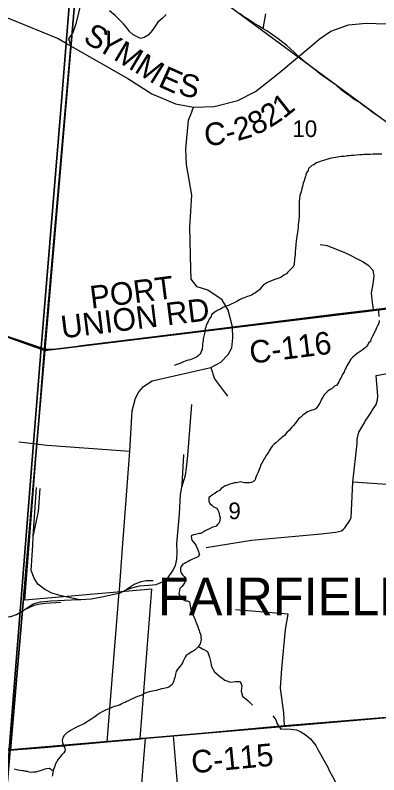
# Model space of a CAD drawing. Extents: x 0 to 34, y 0 to 22.
# Drawn here: x 3.482 to 4.396, y 16.296 to 18.207 of the extents above; entities that cross this region are included whole.
import ezdxf

# ---------------------------------------------------------------- set-up
doc = ezdxf.new("R2010")
doc.units = 0
for name, color, linetype in [('Default', 7, 'Continuous'), ('GM_X_Corporation_Text', 7, 'Continuous'), ('GM_X_County_Road', 7, 'Continuous'), ('GM_X_County_Road_Text', 7, 'Continuous'), ('GM_X_Minor_River', 7, 'Continuous'), ('GM_X_Rail_Line', 7, 'Continuous'), ('GM_X_Section', 7, 'Continuous'), ('GM_X_Section_Text', 7, 'Continuous'), ('GM_X_Township_Road', 7, 'Continuous')]:
    doc.layers.add(name, color=color, linetype=linetype)

msp = doc.modelspace()

# ---------------------------------------------------------------- linework, layer by layer
at = {"layer": 'Default'}
msp.add_lwpolyline([(2.8131, 18.5849), (2.7778, 18.1558), (2.5327, 18.2417), (2.4945, 17.7428), (2.4362, 17.7466), (2.1, 17.6674), (2.1, 15.6423), (2.3082, 15.6745), (2.5606, 15.599), (3.3845, 15.362), (3.4491, 16.1969), (3.7972, 16.2327), (3.8103, 16.3888), (3.7967, 16.3876), (3.8259, 16.7634), (3.5062, 16.7356), (3.5564, 17.3695), (3.6226, 18.1301), (3.6176, 18.1479), (3.628, 18.1636), (3.6366, 18.1888), (3.6479, 18.2377)], dxfattribs=at)
at = {"layer": 'GM_X_County_Road'}
for points in [[(3.0718, 18.2788), (3.1658, 18.2699), (3.2524, 18.2573), (3.3817, 18.2277), (3.4672, 18.1987), (3.5902, 18.1482), (3.6107, 18.1365), (3.6157, 18.1336), (3.627, 18.1271)], [(3.627, 18.1271), (3.7655, 18.0478), (3.8255, 18.0096), (3.8854, 17.9841), (3.9304, 17.9759), (3.9821, 17.9774), (4.0423, 17.9922), (4.0862, 18.0148), (4.1461, 18.0623), (4.223, 18.1271), (4.2464, 18.1466), (4.2759, 18.167), (4.3203, 18.183), (4.3649, 18.1867), (4.441, 18.1842), (4.6746, 18.1631), (4.6846, 18.1624)], [(2.4755, 17.7454), (2.9932, 17.5584), (3.0263, 17.5466), (3.4872, 17.3916), (3.5483, 17.37), (3.5629, 17.3674)], [(3.5629, 17.3674), (3.5638, 17.3673), (3.5831, 17.367), (3.6256, 17.3718), (3.6484, 17.3765), (3.8461, 17.4003), (4.0282, 17.423), (4.2903, 17.4561), (4.3826, 17.4667), (4.417, 17.4713), (4.4983, 17.48), (4.5325, 17.4838), (4.5638, 17.487), (4.5869, 17.4825)], [(3.7629, 16.3834), (3.7923, 16.3861), (3.8158, 16.3891), (3.8791, 16.3942), (3.9679, 16.4025), (4.1131, 16.4161), (4.1592, 16.4206), (4.4147, 16.4416), (4.4965, 16.4435)], [(3.319, 16.3055), (3.3603, 16.3282), (3.383, 16.3393), (3.4061, 16.3477), (3.4239, 16.3525), (3.4362, 16.355), (3.4501, 16.3569), (3.4679, 16.3586), (3.5563, 16.3652), (3.7138, 16.379), (3.7629, 16.3834)]]:
    msp.add_lwpolyline(points, dxfattribs=at)
at = {"layer": 'GM_X_Minor_River'}
for points in [[(3.8622, 18.2087), (3.8516, 18.1987), (3.8407, 18.1896), (3.8276, 18.1691), (3.8162, 18.1572), (3.8065, 18.1511), (3.7977, 18.1487), (3.7891, 18.1528), (3.779, 18.158), (3.7704, 18.1651), (3.7631, 18.1752), (3.7547, 18.185), (3.7447, 18.1955), (3.7333, 18.2065), (3.7195, 18.218)], [(4.4011, 17.9489), (4.3896, 17.9569), (4.3791, 17.9644), (4.3669, 17.9732), (4.3564, 17.9807), (4.3468, 17.9882), (4.3348, 17.9954), (4.3255, 18.0022), (4.314, 18.0101), (4.3021, 18.0196), (4.2891, 18.0314), (4.2791, 18.0378), (4.2668, 18.0469), (4.2575, 18.0533), (4.2474, 18.0604), (4.2363, 18.0695), (4.2266, 18.077), (4.2147, 18.0865), (4.2062, 18.0933), (4.1943, 18.1035), (4.1836, 18.1141), (4.174, 18.1227), (4.1651, 18.1306), (4.1547, 18.1385), (4.1435, 18.1476), (4.1234, 18.1619), (4.1145, 18.1675), (4.1055, 18.1724), (4.0943, 18.1803), (4.0824, 18.1867), (4.0693, 18.1951), (4.0574, 18.2031), (4.0481, 18.2106)], [(4.1055, 18.1724), (4.1123, 18.2105)], [(4.4041, 17.8572), (4.3927, 17.8576), (4.3855, 17.8574), (4.3821, 17.8572), (4.3748, 17.857), (4.3676, 17.8565), (4.3592, 17.8563), (4.3547, 17.8561), (4.3486, 17.8555), (4.3394, 17.855), (4.3333, 17.8545), (4.328, 17.8542), (4.3223, 17.8537), (4.3177, 17.853), (4.3143, 17.8528), (4.3089, 17.8518), (4.3017, 17.8516), (4.2971, 17.8506), (4.2925, 17.85), (4.2872, 17.849), (4.2822, 17.8484), (4.2776, 17.8478), (4.273, 17.8464), (4.2681, 17.845), (4.2627, 17.8433), (4.2569, 17.8416), (4.2516, 17.8399), (4.2473, 17.8385), (4.2435, 17.8374), (4.2381, 17.8346), (4.2331, 17.8309), (4.228, 17.8288), (4.2198, 17.8211), (4.2186, 17.8165), (4.215, 17.8106), (4.2133, 17.8064), (4.2125, 17.803), (4.2112, 17.7996), (4.2087, 17.7906), (4.2066, 17.7846), (4.2057, 17.7808), (4.2045, 17.7763), (4.2032, 17.7714), (4.201, 17.7627), (4.1981, 17.7533), (4.1967, 17.745), (4.1962, 17.7397), (4.196, 17.7332), (4.1965, 17.7267), (4.1959, 17.7051), (4.1961, 17.6994), (4.1956, 17.6952), (4.1955, 17.691), (4.1946, 17.6861), (4.194, 17.6804), (4.1935, 17.6744), (4.1925, 17.6679), (4.1916, 17.6607), (4.1905, 17.6513), (4.1887, 17.6399), (4.1876, 17.6297), (4.187, 17.6206), (4.1863, 17.6119), (4.1857, 17.6047), (4.1852, 17.5986), (4.1847, 17.5944), (4.1841, 17.5895), (4.184, 17.5861), (4.1839, 17.58), (4.181, 17.5744), (4.1759, 17.5692), (4.1712, 17.5644), (4.1665, 17.56), (4.1642, 17.5567), (4.1576, 17.5531), (4.1533, 17.5502), (4.1498, 17.5472), (4.1429, 17.5448), (4.1375, 17.543), (4.1326, 17.5413), (4.1264, 17.5388), (4.1202, 17.536), (4.1148, 17.5335)], [(4.1148, 17.5335), (4.1102, 17.5306), (4.1067, 17.5288), (4.1008, 17.5221), (4.0961, 17.5166), (4.0918, 17.5129), (4.0867, 17.5089), (4.0829, 17.5067), (4.0763, 17.5031), (4.0721, 17.5009), (4.0663, 17.4992), (4.0621, 17.4978), (4.0583, 17.4964), (4.0532, 17.4943), (4.0463, 17.4907), (4.0397, 17.4871), (4.0312, 17.4824), (4.027, 17.481), (4.0189, 17.4771), (4.0155, 17.4757), (4.0089, 17.4736), (4.0047, 17.4718), (3.9981, 17.4675), (3.9916, 17.465), (3.9865, 17.4617), (3.9823, 17.4596), (3.976, 17.4533), (3.9751, 17.4492), (3.9696, 17.4425), (3.9672, 17.4369), (3.9648, 17.432), (3.9627, 17.4267), (3.9614, 17.4226), (3.9602, 17.4181), (3.9596, 17.4128), (3.9579, 17.4064), (3.9574, 17.403), (3.9566, 17.3996), (3.9552, 17.3928), (3.9547, 17.3886), (3.9539, 17.3848), (3.9533, 17.3799), (3.9532, 17.3738), (3.9527, 17.37), (3.9526, 17.3662), (3.9498, 17.3618), (3.9489, 17.358), (3.9461, 17.3546), (3.9422, 17.3506), (3.9383, 17.3473), (3.9341, 17.3451), (3.9264, 17.3416), (3.9222, 17.3405), (3.9179, 17.3392), (3.9137, 17.3381), (3.9053, 17.335), (3.9018, 17.3336), (3.896, 17.3307), (3.891, 17.329), (3.8864, 17.3272), (3.8822, 17.3262)], [(4.3964, 17.4671), (4.3959, 17.4629), (4.3958, 17.4587), (4.396, 17.4534), (4.3967, 17.4488)], [(4.3971, 17.4389), (4.3962, 17.4317), (4.3933, 17.4254), (4.3909, 17.4205), (4.3868, 17.4123), (4.3804, 17.3999), (4.3764, 17.3917), (4.3751, 17.386), (4.3708, 17.3823), (4.3687, 17.3778), (4.366, 17.3745), (4.3621, 17.3704), (4.3586, 17.3679), (4.3547, 17.3646), (4.3469, 17.3595), (4.3419, 17.3562), (4.3368, 17.3518), (4.3309, 17.3467), (4.3259, 17.3415), (4.3203, 17.3322), (4.3171, 17.3266), (4.3142, 17.321), (4.3118, 17.3165), (4.3102, 17.3131), (4.3093, 17.3093), (4.3054, 17.3045), (4.3021, 17.2955), (4.2993, 17.2922), (4.2973, 17.288)], [(4.2973, 17.288), (4.2961, 17.2846), (4.2937, 17.2805), (4.2905, 17.2765), (4.2851, 17.2736), (4.2792, 17.2684), (4.2727, 17.2645), (4.2668, 17.2597), (4.2633, 17.256), (4.2594, 17.2523), (4.2554, 17.246), (4.2526, 17.2411), (4.2477, 17.2314), (4.2457, 17.228), (4.2433, 17.2239), (4.2382, 17.2172), (4.2324, 17.214), (4.2282, 17.2134), (4.2213, 17.2113), (4.2175, 17.2095), (4.2109, 17.2051), (4.2054, 17.2007), (4.2003, 17.1963), (4.1957, 17.1923), (4.1921, 17.1882), (4.1858, 17.1801), (4.1822, 17.1752), (4.1779, 17.1708), (4.1712, 17.1626), (4.1654, 17.1575), (4.1594, 17.1497), (4.1536, 17.1457), (4.1497, 17.142), (4.1458, 17.1387), (4.1376, 17.131), (4.1325, 17.1269), (4.1294, 17.1236), (4.1259, 17.1199), (4.1207, 17.1113), (4.1191, 17.108), (4.1167, 17.1039), (4.1127, 17.099), (4.1103, 17.0949), (4.1083, 17.0912), (4.1055, 17.0863), (4.1019, 17.0804), (4.0987, 17.074), (4.0982, 17.0698), (4.0954, 17.0646), (4.0924, 17.0556), (4.0896, 17.0507), (4.0884, 17.0466), (4.0863, 17.0421), (4.0859, 17.0383), (4.082, 17.0346), (4.0762, 17.0314), (4.0716, 17.0307), (4.067, 17.0305), (4.0624, 17.0306), (4.0587, 17.0311), (4.0553, 17.032), (4.0485, 17.033), (4.042, 17.032), (4.0374, 17.031), (4.0336, 17.0308), (4.0282, 17.0294), (4.0217, 17.0273), (4.0159, 17.0252), (4.0082, 17.022), (4.0047, 17.0187), (3.9997, 17.0166), (3.9957, 17.0114), (3.9892, 17.0078), (3.9841, 17.0041), (3.9791, 17.0012), (3.9737, 16.9968), (3.969, 16.9936), (3.9692, 16.9882), (3.9695, 16.9848), (3.972, 16.979), (3.9764, 16.9743), (3.9801, 16.9712), (3.985, 16.9691), (3.9884, 16.9671), (3.9913, 16.9636), (3.9941, 16.9567), (3.9952, 16.9529), (3.9962, 16.9479), (3.9972, 16.9437), (3.997, 16.9357), (3.9953, 16.93), (3.9913, 16.9256), (3.9874, 16.9219), (3.9763, 16.9185), (3.9705, 16.9148), (3.9651, 16.9127), (3.9601, 16.9098), (3.9547, 16.907), (3.9489, 16.9033), (3.9447, 16.9031), (3.9412, 16.9024)], [(3.9412, 16.9024), (3.9355, 16.9011), (3.9302, 16.9001), (3.9248, 16.8976), (3.9257, 16.8904), (3.9263, 16.8869), (3.93, 16.8826), (3.9344, 16.8764), (3.9369, 16.8725), (3.9398, 16.866), (3.9416, 16.8621), (3.943, 16.8583), (3.944, 16.8548), (3.9458, 16.8502), (3.9426, 16.845), (3.9361, 16.8421), (3.9326, 16.8407), (3.928, 16.8386), (3.9214, 16.8357), (3.9171, 16.8325), (3.9118, 16.8303), (3.9079, 16.8278), (3.904, 16.826), (3.8997, 16.8201), (3.8981, 16.8163), (3.8976, 16.8125), (3.8982, 16.8079), (3.8992, 16.8041), (3.9025, 16.7994), (3.9073, 16.7951), (3.9102, 16.7908), (3.9101, 16.7855), (3.9076, 16.7791), (3.9044, 16.7743), (3.9009, 16.7702), (3.8966, 16.765), (3.8953, 16.7598), (3.8944, 16.7564), (3.8939, 16.7522), (3.8953, 16.7483), (3.8967, 16.7449), (3.8992, 16.7399), (3.9071, 16.7354), (3.9105, 16.7342), (3.9158, 16.7337), (3.9206, 16.7312), (3.9217, 16.727), (3.9223, 16.722), (3.9229, 16.7163), (3.9249, 16.709), (3.9271, 16.704), (3.9299, 16.6975), (3.9317, 16.694), (3.9331, 16.6905), (3.936, 16.6836), (3.9377, 16.6771), (3.9402, 16.6713), (3.943, 16.6636), (3.9452, 16.6594), (3.9454, 16.656), (3.9483, 16.6498), (3.9489, 16.6456), (3.9492, 16.6422), (3.9498, 16.6368), (3.9486, 16.6327), (3.9472, 16.6259), (3.9452, 16.6225), (3.9428, 16.6188), (3.9393, 16.6147), (3.9346, 16.611), (3.9296, 16.607), (3.9261, 16.6056), (3.9168, 16.5998), (3.9125, 16.5961), (3.9098, 16.5924), (3.907, 16.5876), (3.9049, 16.5823), (3.9033, 16.5782), (3.9005, 16.5737), (3.8961, 16.5685), (3.8926, 16.5644), (3.8894, 16.56), (3.887, 16.5562), (3.8857, 16.5494), (3.8844, 16.5445), (3.8835, 16.5408), (3.8823, 16.537), (3.8814, 16.5328), (3.8798, 16.5287), (3.8766, 16.5235), (3.873, 16.5198), (3.8688, 16.5165), (3.8634, 16.5151), (3.8558, 16.5138), (3.8504, 16.5125), (3.8454, 16.5107), (3.8408, 16.5097), (3.8374, 16.5083), (3.832, 16.5077), (3.819, 16.5051), (3.8129, 16.503)], [(3.9428, 16.6188), (3.9532, 16.6136), (3.9659, 16.6064), (3.9709, 16.5922), (3.9729, 16.5819), (3.976, 16.5685), (3.9832, 16.5554), (3.9955, 16.5444), (4.0089, 16.5346), (4.0232, 16.5293), (4.0358, 16.5313), (4.048, 16.5306), (4.0519, 16.5198), (4.05, 16.5066), (4.0539, 16.4943), (4.0669, 16.4833), (4.0792, 16.4716)], [(3.8129, 16.503), (3.8075, 16.5005), (3.8005, 16.4965), (3.7932, 16.4945), (3.7898, 16.4931), (3.7859, 16.4913), (3.7786, 16.4881), (3.7732, 16.4856), (3.7674, 16.4827), (3.7624, 16.4806), (3.7586, 16.4784), (3.7547, 16.477), (3.7489, 16.4738), (3.7443, 16.4716), (3.7405, 16.4706), (3.7363, 16.4692), (3.7313, 16.4679), (3.724, 16.4647), (3.7201, 16.4633), (3.7155, 16.4615), (3.7094, 16.459), (3.7059, 16.4572), (3.7012, 16.4543), (3.6954, 16.4511), (3.6904, 16.4482), (3.6858, 16.4449), (3.6822, 16.442), (3.6776, 16.4387), (3.6725, 16.435), (3.6687, 16.4325), (3.6594, 16.4267), (3.6555, 16.4245), (3.6513, 16.4228), (3.6366, 16.416), (3.6293, 16.412), (3.6227, 16.4088), (3.6177, 16.4052), (3.6134, 16.4026), (3.6099, 16.3997), (3.6048, 16.3945), (3.6028, 16.3904), (3.6016, 16.3867), (3.6007, 16.3829), (3.6009, 16.3779), (3.6027, 16.3722), (3.6045, 16.3679), (3.607, 16.3637), (3.6076, 16.3599), (3.6068, 16.3557), (3.6044, 16.3516), (3.5996, 16.3464), (3.5949, 16.3409), (3.5918, 16.3375), (3.5898, 16.3338), (3.5858, 16.3282), (3.583, 16.3222), (3.5817, 16.3181), (3.5801, 16.3139), (3.5788, 16.3094), (3.5779, 16.3056), (3.5771, 16.3022), (3.5761, 16.2966), (3.5753, 16.2928)], [(4.1298, 16.4445), (4.1379, 16.4344), (4.1411, 16.4248), (4.1502, 16.4109), (4.1635, 16.4117), (4.1757, 16.4113), (4.1893, 16.4091), (4.2006, 16.4042), (4.2114, 16.3975), (4.2248, 16.3865), (4.2381, 16.3698), (4.2431, 16.3598), (4.2501, 16.3486), (4.2548, 16.3386), (4.2617, 16.327), (4.2682, 16.3151), (4.2725, 16.3051), (4.2798, 16.2923), (4.2871, 16.2777)], [(3.5779, 16.3056), (3.5682, 16.312), (3.561, 16.3111), (3.5568, 16.3101), (3.5529, 16.3091), (3.5495, 16.308), (3.5453, 16.3066), (3.5418, 16.3052), (3.5341, 16.3032), (3.5288, 16.3026), (3.5223, 16.3024), (3.5174, 16.3033), (3.5133, 16.3042), (3.5095, 16.3047), (3.5053, 16.306), (3.5008, 16.3065), (3.4951, 16.3074), (3.4902, 16.3079), (3.4864, 16.3088), (3.4804, 16.3101)]]:
    msp.add_lwpolyline(points, dxfattribs=at)
at = {"layer": 'GM_X_Rail_Line'}
msp.add_line((3.5277, 16.8958), (3.5358, 17.0191), dxfattribs=at)
for points in [[(5.5527, 16.4145), (5.3725, 16.7649), (5.3098, 16.8872), (5.1812, 17.1373), (5.0499, 17.393), (5.037, 17.4166), (5.0252, 17.437), (5.0139, 17.4546), (5.001, 17.4731), (4.9895, 17.4883), (4.9752, 17.5053), (4.9605, 17.5218), (4.9371, 17.5451), (4.921, 17.5598), (4.9044, 17.5741), (4.8871, 17.5886), (4.8723, 17.5997), (4.7884, 17.6623), (4.6417, 17.7708), (4.3528, 17.9844), (3.8782, 18.3346)], [(3.9015, 17.0197), (3.9103, 17.05), (3.9133, 17.0684), (3.9166, 17.0993), (3.9261, 17.2276)], [(3.9015, 17.0197), (3.9031, 17.0398), (3.9064, 17.1023)], [(3.5277, 16.8958), (3.5362, 16.9349), (3.5408, 16.9589), (3.5454, 17.0168)], [(3.7614, 16.7613), (3.7759, 16.7669), (3.7949, 16.7718), (3.8186, 16.7731), (3.8367, 16.7751), (3.8528, 16.7817), (3.8669, 16.7929), (3.8781, 16.8083), (3.885, 16.8228), (3.8886, 16.8386), (3.8893, 16.8573), (3.889, 16.8777), (3.8952, 16.953), (3.8982, 17.0013), (3.9015, 17.0197)], [(3.6405, 16.737), (3.598, 16.7462), (3.5746, 16.7531), (3.5572, 16.7626), (3.5395, 16.7761), (3.5299, 16.7906), (3.5227, 16.81), (3.5263, 16.8738), (3.5277, 16.8958)], [(3.8291, 16.7846), (3.812, 16.7843), (3.7956, 16.781), (3.7815, 16.7754), (3.7614, 16.7613)], [(3.6405, 16.737), (3.647, 16.7373), (3.6736, 16.7393), (3.7002, 16.7439), (3.7463, 16.7541), (3.7614, 16.7613)], [(2.9436, 16.7403), (2.9614, 16.7301), (2.9818, 16.7212), (2.9986, 16.7189), (3.0236, 16.7195), (3.0558, 16.7212), (3.0765, 16.7225), (3.111, 16.7202), (3.4342, 16.6936), (3.4559, 16.6926), (3.4717, 16.6949), (3.4859, 16.6998), (3.5046, 16.7113)], [(3.5046, 16.7113), (3.5279, 16.7268), (3.5464, 16.7317), (3.5723, 16.734), (3.6405, 16.737)], [(3.5046, 16.7113), (3.5302, 16.7232), (3.545, 16.7261), (3.5582, 16.7284), (3.5967, 16.7307)]]:
    msp.add_lwpolyline(points, dxfattribs=at)
at = {"layer": 'GM_X_Section'}
msp.add_lwpolyline([(2.6081, 18.801), (3.6423, 18.3609), (3.5572, 17.3639), (2.4678, 17.7524), (2.5533, 18.801)], dxfattribs=at)
for points in [[(4.6831, 18.5192), (4.5906, 17.4897), (3.5572, 17.3639), (3.6423, 18.3609)], [(2.4678, 17.7524), (3.5572, 17.3639), (3.4704, 16.3589), (2.3835, 16.7168)], [(3.5572, 17.3639), (4.5906, 17.4897), (4.4981, 16.447), (3.4704, 16.3589)], [(4.4981, 16.447), (4.4056, 15.4266), (3.385, 15.3645), (3.4704, 16.3589)]]:
    msp.add_lwpolyline(points, close=True, dxfattribs=at)
at = {"layer": 'GM_X_Township_Road'}
msp.add_line((4.5451, 17.0182), (4.3312, 17.0322), dxfattribs=at)
for points in [[(2.1, 18.801), (2.1, 15.6427), (2.3082, 15.6745), (2.4145, 15.6427), (2.5606, 15.599), (3.3455, 15.3733), (3.3845, 15.362), (3.4311, 15.9332), (3.4604, 16.2167), (3.4676, 16.3592), (3.5285, 17.1302), (3.548, 17.3706), (3.5984, 17.9897), (3.6087, 18.1157), (3.6104, 18.137), (3.6645, 18.801)], [(3.6645, 18.801), (3.6104, 18.137), (3.6087, 18.1157), (3.5984, 17.9897), (3.548, 17.3706), (3.5285, 17.1302), (3.4676, 16.3592)], [(4.0282, 17.423), (4.018, 17.4653), (4.0027, 17.491), (3.9665, 17.5156), (3.9395, 17.5235), (3.925, 17.5431), (3.9236, 17.5689), (3.9211, 17.6743), (3.926, 17.754), (3.9133, 17.8314), (3.9109, 17.8698), (3.9184, 17.9432), (3.9236, 17.9574), (3.9304, 17.9759)], [(4.3826, 17.4667), (4.3809, 17.4846), (4.3778, 17.5081), (4.383, 17.5367), (4.385, 17.5516), (4.3819, 17.5649), (4.3716, 17.5764), (4.3541, 17.5873), (4.3153, 17.6079), (4.2671, 17.627), (4.2493, 17.6291)], [(3.7554, 16.9111), (3.7601, 16.9767), (3.7705, 17.1104), (3.7765, 17.2116), (3.785, 17.2437), (3.7935, 17.26), (3.805, 17.2727), (3.8268, 17.2873), (3.9739, 17.3206), (3.9993, 17.3339), (4.0181, 17.3539), (4.0267, 17.3705), (4.0298, 17.3953), (4.0282, 17.423)], [(3.9739, 17.3206), (3.983, 17.2927), (4.0163, 17.2485)], [(4.379, 17.2115), (4.3898, 17.2282), (4.3934, 17.2397), (4.394, 17.2497), (4.3895, 17.3009), (4.4313, 17.3085), (4.4712, 17.3124), (4.5115, 17.3157), (4.5731, 17.3208)], [(3.9627, 16.8677), (4.0761, 16.8865), (4.2512, 16.9021), (4.2874, 16.9063), (4.3027, 16.9098), (4.308, 16.9139), (4.3109, 16.9177), (4.3236, 16.9361), (4.3265, 16.9438), (4.3312, 17.0322), (4.3417, 17.1295), (4.3423, 17.1407), (4.3459, 17.1583), (4.361, 17.1834), (4.362, 17.1862), (4.3698, 17.1967), (4.3777, 17.2095), (4.379, 17.2115)], [(3.4914, 17.1341), (3.5287, 17.1296), (3.5407, 17.1282)], [(3.5407, 17.1282), (3.5628, 17.1256), (3.7705, 17.1104)], [(3.7442, 16.7606), (3.7523, 16.8676), (3.7554, 16.9111)], [(3.7138, 16.379), (3.7438, 16.7556), (3.7442, 16.7606)], [(4.1592, 16.4206), (4.1573, 16.4522), (4.1489, 16.514), (4.1525, 16.5636), (4.1622, 16.6617), (4.1682, 16.7005), (4.0362, 16.7114)], [(3.8791, 16.3942), (3.9048, 16.0923), (3.9118, 16.0639), (3.9215, 16.031), (3.9321, 15.9959)]]:
    msp.add_lwpolyline(points, dxfattribs=at)

# ---------------------------------------------------------------- texts
at = {"layer": 'GM_X_Corporation_Text'}
msp.add_text('FAIRFIELD', height=0.0947, rotation=0, dxfattribs=at).set_placement((3.8414, 16.6976))
at = {"layer": 'GM_X_County_Road_Text'}
for s, height, rotation, p in [('S', 0.0568, 329.6499, (3.6504, 18.1415)), ('Y', 0.0568, 329.6494, (3.6835, 18.1222)), ('M', 0.0568, 329.3288, (3.7266, 18.0969)), ('M', 0.0568, 328.1485, (3.7793, 18.0657)), ('E', 0.0568, 335.7736, (3.839, 18.0292)), ('S', 0.0568, 347.4994, (3.8898, 18.0078)), ('1', 0.0568, 38.191, (4.1567, 17.9451)), ('2', 0.0568, 33.0127, (4.1228, 17.9228)), ('8', 0.0568, 25.9296, (4.0847, 17.9037)), ('2', 0.0568, 16.1025, (4.0411, 17.8902)), ('C', 0.0568, 4.2288, (3.9594, 17.8786)), ('-', 0.0568, 14.7043, (4.0171, 17.8839)), ('PORT', 0.05682, 7.2916, (3.6739, 17.4688)), ('UNION RD', 0.05682, 7.0697, (3.6007, 17.3939)), ('C-116', 0.05682, 7.1932, (4.0748, 17.3301)), ('C-115', 0.05682, 5.491, (3.9276, 16.2997))]:
    msp.add_text(s, height=height, rotation=rotation, dxfattribs=at).set_placement(p)
at = {"layer": 'GM_X_Section_Text'}
for s, height, p in [('10', 0.04186, (4.1791, 17.9006)), ('9', 0.0419, (4.0183, 16.9394))]:
    msp.add_text(s, height=height, rotation=0, dxfattribs=at).set_placement(p)

doc.saveas('drawing.dxf')
